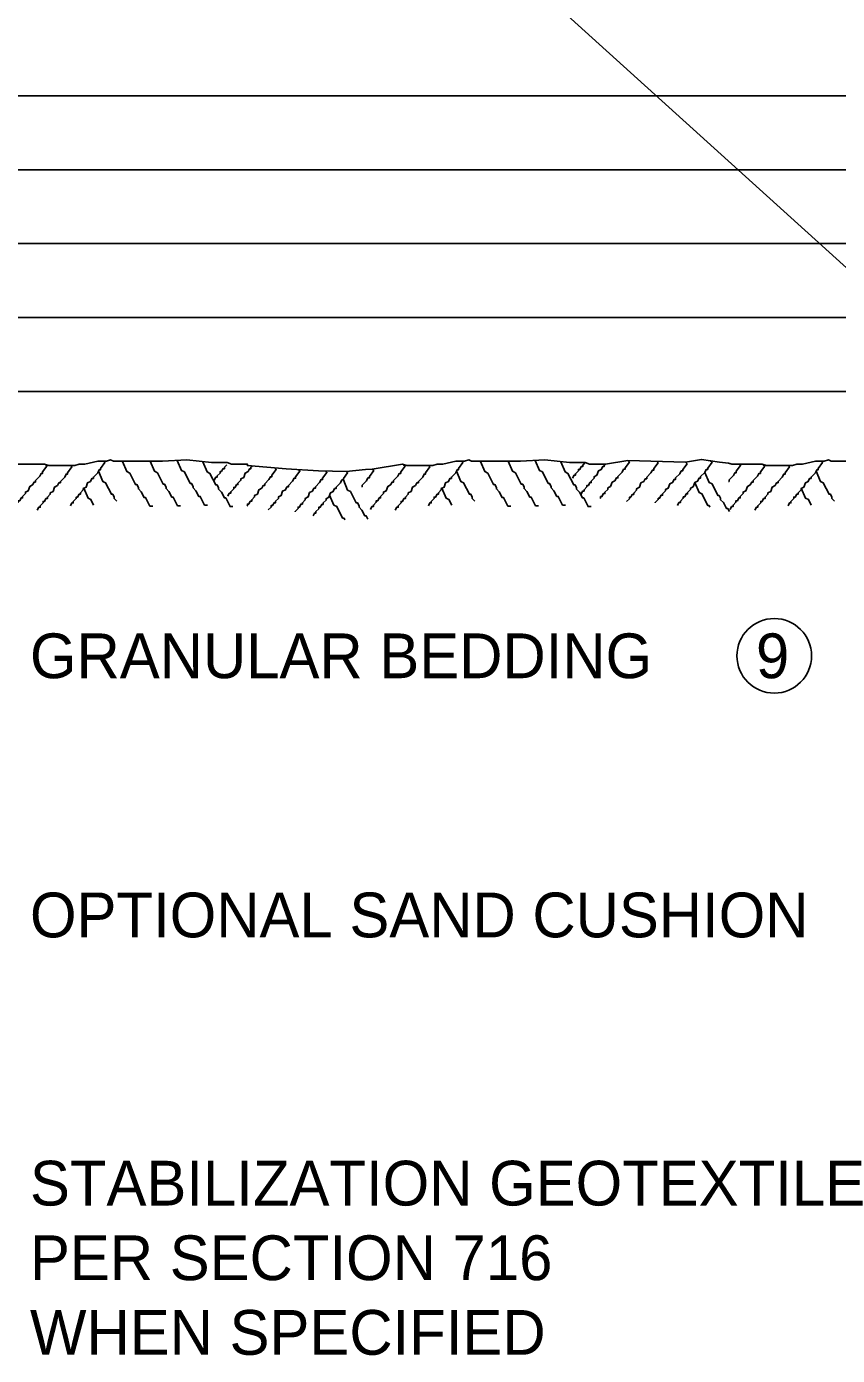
# Model space of a CAD drawing. Extents: x 49991.4 to 50021, y 49987.6 to 50011.4.
# Drawn here: x 50014.432 to 50015.519, y 50004.647 to 50006.427 of the extents above; entities that cross this region are included whole.
import ezdxf

# ---------------------------------------------------------------- set-up
doc = ezdxf.new("R2010")
doc.units = 0
doc.layers.add('Level 1', color=7, linetype='Continuous')
doc.layers.add('Level 2', color=7, linetype='Continuous')

msp = doc.modelspace()

# ---------------------------------------------------------------- linework, layer by layer
at = {"layer": 'Level 1'}
for p, q in [((50015.8403, 50005.8238), (50013.8839, 50007.5958)), ((50015.7342, 50006.3346), (50013.9592, 50006.3346)), ((50015.7342, 50006.2356), (50013.9592, 50006.2356)), ((50015.7342, 50006.1366), (50013.9592, 50006.1366)), ((50015.7342, 50006.0376), (50014.2021, 50006.0376)), ((50015.7342, 50005.9386), (50014.3195, 50005.9386))]:
    msp.add_line(p, q, dxfattribs=at)
for points in [[(50014.4579, 50005.8402), (50014.4598, 50005.8383), (50014.454, 50005.8306), (50014.454, 50005.8286), (50014.4522, 50005.8286), (50014.4502, 50005.8248), (50014.4444, 50005.819), (50014.4444, 50005.8171), (50014.4425, 50005.8171), (50014.4406, 50005.8132), (50014.4367, 50005.8113), (50014.4347, 50005.8055), (50014.4309, 50005.8036), (50014.4309, 50005.8016), (50014.427, 50005.7978), (50014.427, 50005.7959), (50014.4251, 50005.7959), (50014.4232, 50005.792), (50014.4213, 50005.792), (50014.4213, 50005.7901), (50014.4174, 50005.7862), (50014.4174, 50005.7843), (50014.4155, 50005.7843), (50014.4135, 50005.7805)], [(50014.4159, 50005.8412), (50014.4565, 50005.8412), (50014.4623, 50005.8392), (50014.497, 50005.8392), (50014.5028, 50005.8412), (50014.5105, 50005.8412), (50014.5278, 50005.845), (50014.5394, 50005.845), (50014.5451, 50005.8469), (50014.549, 50005.845), (50014.6088, 50005.845), (50014.6146, 50005.845), (50014.6474, 50005.8469), (50014.6801, 50005.8431), (50014.7013, 50005.8431), (50014.7071, 50005.8412), (50014.7206, 50005.8412), (50014.7283, 50005.8412), (50014.7283, 50005.8392), (50014.7801, 50005.8346), (50014.8235, 50005.832), (50014.8422, 50005.8317), (50014.8606, 50005.8314), (50014.8865, 50005.834)], [(50014.4912, 50005.8393), (50014.4931, 50005.8373), (50014.4873, 50005.8296), (50014.4873, 50005.8277), (50014.4854, 50005.8277), (50014.4835, 50005.8238), (50014.4777, 50005.818), (50014.4777, 50005.8161), (50014.4757, 50005.8161), (50014.4738, 50005.8123), (50014.47, 50005.8103), (50014.468, 50005.8046), (50014.4642, 50005.8026), (50014.4642, 50005.8007), (50014.4603, 50005.7969), (50014.4603, 50005.7949), (50014.4584, 50005.7949), (50014.4565, 50005.7911), (50014.4545, 50005.7911), (50014.4545, 50005.7891), (50014.4507, 50005.7853), (50014.4507, 50005.7834), (50014.4487, 50005.7834), (50014.4468, 50005.7795)], [(50014.5355, 50005.845), (50014.5374, 50005.8431), (50014.5317, 50005.8354), (50014.5317, 50005.8335), (50014.5297, 50005.8335), (50014.5278, 50005.8296), (50014.522, 50005.8238), (50014.522, 50005.8219), (50014.5201, 50005.8219), (50014.5181, 50005.818), (50014.5143, 50005.8161), (50014.5123, 50005.8103), (50014.5085, 50005.8084), (50014.5085, 50005.8065), (50014.5046, 50005.8026), (50014.5046, 50005.8007), (50014.5027, 50005.8007), (50014.5008, 50005.7969), (50014.4989, 50005.7969), (50014.4989, 50005.7949), (50014.495, 50005.7911), (50014.495, 50005.7891), (50014.4931, 50005.7891), (50014.4912, 50005.7853)], [(50014.5288, 50005.8315), (50014.5345, 50005.818), (50014.5384, 50005.8161), (50014.5461, 50005.8007), (50014.548, 50005.8007), (50014.55, 50005.7968), (50014.55, 50005.7949), (50014.5535, 50005.7914)], [(50014.5611, 50005.8446), (50014.5668, 50005.8311), (50014.5707, 50005.8291), (50014.5784, 50005.8137), (50014.5804, 50005.8137), (50014.5822, 50005.8098), (50014.5822, 50005.8079), (50014.5861, 50005.8041), (50014.59, 50005.7963), (50014.5919, 50005.7963), (50014.5977, 50005.7848), (50014.6015, 50005.7848)], [(50014.5981, 50005.845), (50014.6039, 50005.8315), (50014.6078, 50005.8296), (50014.6155, 50005.8142), (50014.6174, 50005.8142), (50014.6194, 50005.8103), (50014.6194, 50005.8084), (50014.6232, 50005.8046), (50014.6271, 50005.7968), (50014.629, 50005.7968), (50014.6348, 50005.7853), (50014.6387, 50005.7853)], [(50014.6343, 50005.846), (50014.6401, 50005.8325), (50014.6439, 50005.8306), (50014.6517, 50005.8152), (50014.6536, 50005.8152), (50014.6555, 50005.8113), (50014.6555, 50005.8094), (50014.6594, 50005.8055), (50014.6632, 50005.7978), (50014.6652, 50005.7978), (50014.6709, 50005.7862), (50014.6748, 50005.7862)], [(50014.6685, 50005.8441), (50014.6743, 50005.8306), (50014.6782, 50005.8286), (50014.6859, 50005.8132), (50014.6878, 50005.8132), (50014.6898, 50005.8094), (50014.6898, 50005.8074), (50014.6936, 50005.8036), (50014.6975, 50005.7959), (50014.6994, 50005.7959), (50014.7052, 50005.7843), (50014.709, 50005.7843)], [(50014.7009, 50005.8403), (50014.6975, 50005.8368), (50014.6975, 50005.8349), (50014.6955, 50005.8349), (50014.6936, 50005.8311), (50014.6917, 50005.8311), (50014.6917, 50005.8291), (50014.6878, 50005.8253), (50014.6878, 50005.8234), (50014.6859, 50005.8234), (50014.684, 50005.8195)], [(50014.7347, 50005.8384), (50014.7331, 50005.8368), (50014.7331, 50005.8349), (50014.7312, 50005.8349), (50014.7292, 50005.8311), (50014.7254, 50005.8291), (50014.7234, 50005.8233), (50014.7196, 50005.8214), (50014.7196, 50005.8194), (50014.7157, 50005.8156), (50014.7157, 50005.8137), (50014.7138, 50005.8137), (50014.7119, 50005.8098), (50014.71, 50005.8098), (50014.71, 50005.8079), (50014.7061, 50005.804), (50014.7061, 50005.8021), (50014.7041, 50005.8021), (50014.7022, 50005.7982)], [(50014.765, 50005.8357), (50014.7669, 50005.8338), (50014.7611, 50005.8261), (50014.7611, 50005.8242), (50014.7592, 50005.8242), (50014.7572, 50005.8203), (50014.7515, 50005.8145), (50014.7515, 50005.8126), (50014.7495, 50005.8126), (50014.7476, 50005.8087), (50014.7438, 50005.8068), (50014.7418, 50005.801), (50014.7379, 50005.7991), (50014.7379, 50005.7972), (50014.7341, 50005.7933), (50014.7341, 50005.7914), (50014.7322, 50005.7914), (50014.7302, 50005.7875), (50014.7283, 50005.7875), (50014.7283, 50005.7856), (50014.7277, 50005.785)], [(50014.7968, 50005.8338), (50014.7987, 50005.8318), (50014.7929, 50005.8241), (50014.7929, 50005.8222), (50014.791, 50005.8222), (50014.789, 50005.8184), (50014.7833, 50005.8126), (50014.7833, 50005.8106), (50014.7814, 50005.8106), (50014.7794, 50005.8068), (50014.7756, 50005.8049), (50014.7736, 50005.799), (50014.7698, 50005.7971), (50014.7698, 50005.7952), (50014.766, 50005.7913), (50014.766, 50005.7894), (50014.764, 50005.7894), (50014.7621, 50005.7856), (50014.7601, 50005.7856), (50014.7601, 50005.7836), (50014.7562, 50005.7798)], [(50014.8329, 50005.8318), (50014.8348, 50005.8299), (50014.829, 50005.8222), (50014.829, 50005.8203), (50014.8271, 50005.8203), (50014.8251, 50005.8164), (50014.8194, 50005.8106), (50014.8194, 50005.8087), (50014.8174, 50005.8087), (50014.8155, 50005.8048), (50014.8117, 50005.8029), (50014.8097, 50005.7971), (50014.8058, 50005.7952), (50014.8058, 50005.7932), (50014.802, 50005.7894), (50014.802, 50005.7875), (50014.8001, 50005.7875), (50014.7982, 50005.7836), (50014.7962, 50005.7836), (50014.7962, 50005.7817), (50014.7924, 50005.7778), (50014.7924, 50005.7772)], [(50014.8606, 50005.8314), (50014.8626, 50005.8295), (50014.8569, 50005.8218), (50014.8569, 50005.8199), (50014.8549, 50005.8199), (50014.853, 50005.816), (50014.8472, 50005.8102), (50014.8472, 50005.8083), (50014.8452, 50005.8083), (50014.8433, 50005.8044), (50014.8395, 50005.8025), (50014.8376, 50005.7967), (50014.8337, 50005.7948), (50014.8337, 50005.7928), (50014.8298, 50005.789), (50014.8298, 50005.7871), (50014.8279, 50005.7871), (50014.826, 50005.7832), (50014.824, 50005.7832), (50014.824, 50005.7813), (50014.8202, 50005.7774), (50014.8202, 50005.7755), (50014.8182, 50005.7755), (50014.8164, 50005.7716)], [(50014.8957, 50005.8343), (50014.8976, 50005.8324), (50014.8918, 50005.8247), (50014.8918, 50005.8227), (50014.8899, 50005.8227), (50014.888, 50005.8189), (50014.8822, 50005.8131), (50014.8822, 50005.8111), (50014.8812, 50005.8111)], [(50014.8865, 50005.834), (50014.8957, 50005.8343), (50014.9362, 50005.8412), (50014.942, 50005.8392), (50014.9767, 50005.8392), (50014.9825, 50005.8412), (50014.9902, 50005.8412), (50015.0075, 50005.845), (50015.0191, 50005.845), (50015.0249, 50005.8469), (50015.0288, 50005.845), (50015.0885, 50005.845), (50015.0943, 50005.845), (50015.1271, 50005.8469), (50015.1599, 50005.8431), (50015.1811, 50005.8431), (50015.1868, 50005.8412), (50015.2003, 50005.8412), (50015.208, 50005.8412), (50015.2383, 50005.8459), (50015.3154, 50005.8436), (50015.3367, 50005.8473), (50015.3611, 50005.8436), (50015.3728, 50005.8424), (50015.3752, 50005.8418)], [(50014.9376, 50005.8402), (50014.9396, 50005.8383), (50014.9338, 50005.8306), (50014.9338, 50005.8286), (50014.9319, 50005.8286), (50014.9299, 50005.8248), (50014.9242, 50005.819), (50014.9242, 50005.8171), (50014.9222, 50005.8171), (50014.9203, 50005.8132), (50014.9164, 50005.8113), (50014.9145, 50005.8055), (50014.9106, 50005.8036), (50014.9106, 50005.8016), (50014.9068, 50005.7978), (50014.9068, 50005.7959), (50014.9049, 50005.7959), (50014.903, 50005.792), (50014.901, 50005.792), (50014.901, 50005.7901), (50014.8971, 50005.7862), (50014.8971, 50005.7843), (50014.8952, 50005.7843), (50014.8933, 50005.7805)], [(50014.9709, 50005.8393), (50014.9728, 50005.8373), (50014.967, 50005.8296), (50014.967, 50005.8277), (50014.9651, 50005.8277), (50014.9632, 50005.8238), (50014.9574, 50005.818), (50014.9574, 50005.8161), (50014.9554, 50005.8161), (50014.9535, 50005.8123), (50014.9497, 50005.8103), (50014.9477, 50005.8046), (50014.9439, 50005.8026), (50014.9439, 50005.8007), (50014.94, 50005.7969), (50014.94, 50005.7949), (50014.9381, 50005.7949), (50014.9362, 50005.7911), (50014.9343, 50005.7911), (50014.9343, 50005.7891), (50014.9304, 50005.7853), (50014.9304, 50005.7834), (50014.9284, 50005.7834), (50014.9265, 50005.7795)], [(50015.0152, 50005.845), (50015.0171, 50005.8431), (50015.0114, 50005.8354), (50015.0114, 50005.8335), (50015.0094, 50005.8335), (50015.0075, 50005.8296), (50015.0017, 50005.8238), (50015.0017, 50005.8219), (50014.9998, 50005.8219), (50014.9979, 50005.818), (50014.994, 50005.8161), (50014.9921, 50005.8103), (50014.9882, 50005.8084), (50014.9882, 50005.8065), (50014.9844, 50005.8026), (50014.9844, 50005.8007), (50014.9825, 50005.8007), (50014.9805, 50005.7969), (50014.9786, 50005.7969), (50014.9786, 50005.7949), (50014.9748, 50005.7911), (50014.9748, 50005.7891), (50014.9728, 50005.7891), (50014.9709, 50005.7853)], [(50015.0085, 50005.8315), (50015.0143, 50005.818), (50015.0181, 50005.8161), (50015.0258, 50005.8007), (50015.0278, 50005.8007), (50015.0297, 50005.7968), (50015.0297, 50005.7949), (50015.0333, 50005.7914)], [(50015.0408, 50005.8446), (50015.0465, 50005.8311), (50015.0504, 50005.8291), (50015.0581, 50005.8137), (50015.0601, 50005.8137), (50015.062, 50005.8098), (50015.062, 50005.8079), (50015.0658, 50005.8041), (50015.0697, 50005.7963), (50015.0716, 50005.7963), (50015.0774, 50005.7848), (50015.0813, 50005.7848)], [(50015.0779, 50005.845), (50015.0837, 50005.8315), (50015.0875, 50005.8296), (50015.0952, 50005.8142), (50015.0972, 50005.8142), (50015.0991, 50005.8103), (50015.0991, 50005.8084), (50015.103, 50005.8046), (50015.1068, 50005.7968), (50015.1087, 50005.7968), (50015.1145, 50005.7853), (50015.1184, 50005.7853)], [(50015.114, 50005.846), (50015.1198, 50005.8325), (50015.1237, 50005.8306), (50015.1314, 50005.8152), (50015.1333, 50005.8152), (50015.1352, 50005.8113), (50015.1352, 50005.8094), (50015.1391, 50005.8055), (50015.143, 50005.7978), (50015.1449, 50005.7978), (50015.1507, 50005.7862), (50015.1545, 50005.7862)], [(50015.1483, 50005.8441), (50015.154, 50005.8306), (50015.1579, 50005.8286), (50015.1656, 50005.8132), (50015.1675, 50005.8132), (50015.1695, 50005.8094), (50015.1695, 50005.8074), (50015.1733, 50005.8036), (50015.1772, 50005.7959), (50015.1791, 50005.7959), (50015.1849, 50005.7843), (50015.1888, 50005.7843)], [(50015.1811, 50005.8431), (50015.1776, 50005.8396), (50015.1776, 50005.8377), (50015.1756, 50005.8377), (50015.1738, 50005.8339), (50015.1718, 50005.8339), (50015.1718, 50005.8319), (50015.1679, 50005.8281), (50015.1679, 50005.8262), (50015.166, 50005.8262), (50015.1641, 50005.8223)], [(50015.208, 50005.8412), (50015.2064, 50005.8396), (50015.2064, 50005.8377), (50015.2045, 50005.8377), (50015.2026, 50005.8338), (50015.1988, 50005.8319), (50015.1968, 50005.8261), (50015.1929, 50005.8242), (50015.1929, 50005.8222), (50015.1891, 50005.8184), (50015.1891, 50005.8164), (50015.1872, 50005.8164), (50015.1852, 50005.8126), (50015.1833, 50005.8126), (50015.1833, 50005.8107), (50015.1795, 50005.8068), (50015.1795, 50005.8049), (50015.1775, 50005.8049), (50015.1756, 50005.801)], [(50015.2383, 50005.8459), (50015.2402, 50005.8439), (50015.2344, 50005.8362), (50015.2344, 50005.8343), (50015.2325, 50005.8343), (50015.2305, 50005.8304), (50015.2248, 50005.8246), (50015.2248, 50005.8227), (50015.2228, 50005.8227), (50015.2209, 50005.8189), (50015.2171, 50005.8169), (50015.2151, 50005.8112), (50015.2113, 50005.8092), (50015.2113, 50005.8073), (50015.2074, 50005.8035), (50015.2074, 50005.8016), (50015.2055, 50005.8016), (50015.2035, 50005.7977), (50015.2017, 50005.7977), (50015.2017, 50005.7957), (50015.201, 50005.7951)], [(50015.2769, 50005.8448), (50015.2788, 50005.8428), (50015.273, 50005.8351), (50015.273, 50005.8332), (50015.2711, 50005.8332), (50015.2691, 50005.8293), (50015.2634, 50005.8236), (50015.2634, 50005.8216), (50015.2614, 50005.8216), (50015.2595, 50005.8178), (50015.2556, 50005.8159), (50015.2537, 50005.81), (50015.2499, 50005.8081), (50015.2499, 50005.8062), (50015.246, 50005.8023), (50015.246, 50005.8004), (50015.2441, 50005.8004), (50015.2421, 50005.7966), (50015.2402, 50005.7966), (50015.2402, 50005.7946), (50015.2363, 50005.7908)], [(50015.3154, 50005.8436), (50015.3174, 50005.8417), (50015.3116, 50005.834), (50015.3116, 50005.8321), (50015.3097, 50005.8321), (50015.3077, 50005.8282), (50015.302, 50005.8225), (50015.302, 50005.8205), (50015.3, 50005.8205), (50015.2981, 50005.8166), (50015.2943, 50005.8147), (50015.2923, 50005.8089), (50015.2884, 50005.807), (50015.2884, 50005.8051), (50015.2846, 50005.8012), (50015.2846, 50005.7993), (50015.2827, 50005.7993), (50015.2807, 50005.7954), (50015.2788, 50005.7954), (50015.2788, 50005.7935), (50015.2749, 50005.7896), (50015.2749, 50005.789)], [(50015.3489, 50005.8455), (50015.3509, 50005.8435), (50015.3452, 50005.8358), (50015.3452, 50005.8339), (50015.3432, 50005.8339), (50015.3413, 50005.83), (50015.3355, 50005.8243), (50015.3355, 50005.8223), (50015.3335, 50005.8223), (50015.3316, 50005.8184), (50015.3277, 50005.8165), (50015.3258, 50005.8108), (50015.322, 50005.8088), (50015.322, 50005.8069), (50015.3181, 50005.803), (50015.3181, 50005.8011), (50015.3162, 50005.8011), (50015.3143, 50005.7972), (50015.3123, 50005.7972), (50015.3123, 50005.7953), (50015.3085, 50005.7914), (50015.3085, 50005.7895), (50015.3065, 50005.7895), (50015.3047, 50005.7857)], [(50015.3728, 50005.8424), (50015.3776, 50005.8412), (50015.4181, 50005.8412), (50015.4239, 50005.8392), (50015.4587, 50005.8392), (50015.4644, 50005.8412), (50015.4721, 50005.8412), (50015.4895, 50005.845), (50015.501, 50005.845), (50015.5068, 50005.8469), (50015.5107, 50005.845), (50015.5704, 50005.845)], [(50015.3873, 50005.8412), (50015.3892, 50005.8393), (50015.3834, 50005.8315), (50015.3834, 50005.8296), (50015.3815, 50005.8296), (50015.3796, 50005.8258), (50015.3738, 50005.82), (50015.3738, 50005.818), (50015.3728, 50005.818)], [(50015.4196, 50005.8402), (50015.4215, 50005.8383), (50015.4157, 50005.8306), (50015.4157, 50005.8286), (50015.4138, 50005.8286), (50015.4119, 50005.8248), (50015.4061, 50005.819), (50015.4061, 50005.8171), (50015.4042, 50005.8171), (50015.4022, 50005.8132), (50015.3984, 50005.8113), (50015.3964, 50005.8055), (50015.3926, 50005.8036), (50015.3926, 50005.8016), (50015.3887, 50005.7978), (50015.3887, 50005.7959), (50015.3868, 50005.7959), (50015.3849, 50005.792), (50015.3829, 50005.792), (50015.3829, 50005.7901), (50015.3791, 50005.7862), (50015.3791, 50005.7843), (50015.3771, 50005.7843), (50015.3752, 50005.7805)], [(50015.4528, 50005.8393), (50015.4547, 50005.8373), (50015.449, 50005.8296), (50015.449, 50005.8277), (50015.447, 50005.8277), (50015.4451, 50005.8238), (50015.4394, 50005.818), (50015.4394, 50005.8161), (50015.4374, 50005.8161), (50015.4355, 50005.8123), (50015.4316, 50005.8103), (50015.4297, 50005.8046), (50015.4258, 50005.8026), (50015.4258, 50005.8007), (50015.422, 50005.7969), (50015.422, 50005.7949), (50015.4201, 50005.7949), (50015.4181, 50005.7911), (50015.4162, 50005.7911), (50015.4162, 50005.7891), (50015.4123, 50005.7853), (50015.4123, 50005.7834), (50015.4104, 50005.7834), (50015.4085, 50005.7795)], [(50015.4972, 50005.845), (50015.4991, 50005.8431), (50015.4933, 50005.8354), (50015.4933, 50005.8335), (50015.4914, 50005.8335), (50015.4895, 50005.8296), (50015.4837, 50005.8238), (50015.4837, 50005.8219), (50015.4817, 50005.8219), (50015.4798, 50005.818), (50015.476, 50005.8161), (50015.474, 50005.8103), (50015.4702, 50005.8084), (50015.4702, 50005.8065), (50015.4663, 50005.8026), (50015.4663, 50005.8007), (50015.4644, 50005.8007), (50015.4624, 50005.7969), (50015.4605, 50005.7969), (50015.4605, 50005.7949), (50015.4567, 50005.7911), (50015.4567, 50005.7891), (50015.4547, 50005.7891), (50015.4528, 50005.7853)], [(50015.4904, 50005.8315), (50015.4962, 50005.818), (50015.5, 50005.8161), (50015.5078, 50005.8007), (50015.5097, 50005.8007), (50015.5116, 50005.7968), (50015.5116, 50005.7949), (50015.5152, 50005.7914)], [(50014.8569, 50005.8199), (50014.8626, 50005.8064), (50014.8665, 50005.8044), (50014.8742, 50005.789), (50014.8761, 50005.789), (50014.8781, 50005.7851), (50014.8781, 50005.7832), (50014.8819, 50005.7794), (50014.8858, 50005.7717), (50014.8877, 50005.7717), (50014.8899, 50005.7673)], [(50015.3277, 50005.8165), (50015.3335, 50005.803), (50015.3374, 50005.8011), (50015.3451, 50005.7857), (50015.3471, 50005.7857), (50015.3481, 50005.7835)], [(50015.3413, 50005.83), (50015.347, 50005.8165), (50015.3509, 50005.8146), (50015.3586, 50005.7991), (50015.3605, 50005.7991), (50015.3625, 50005.7953), (50015.3625, 50005.7934), (50015.3663, 50005.7895), (50015.3702, 50005.7818), (50015.3721, 50005.7818), (50015.3743, 50005.7774)], [(50014.509, 50005.8089), (50014.5148, 50005.7954), (50014.5186, 50005.7935), (50014.5223, 50005.786)], [(50014.8385, 50005.7996), (50014.8443, 50005.7861), (50014.8482, 50005.7842), (50014.8558, 50005.7688), (50014.8578, 50005.7688), (50014.8589, 50005.7666)], [(50014.9887, 50005.8089), (50014.9945, 50005.7954), (50014.9984, 50005.7935), (50015.0021, 50005.786)], [(50015.4706, 50005.8089), (50015.4764, 50005.7954), (50015.4803, 50005.7935), (50015.484, 50005.786)]]:
    msp.add_lwpolyline(points, dxfattribs=at)
at = {"layer": 'Level 2'}
msp.add_circle((50015.4343, 50005.5842), 0.05, dxfattribs=at)

# ---------------------------------------------------------------- texts
for s, p in [('GRANULAR BEDDING', (50014.437, 50005.5542)), ('9', (50015.4098, 50005.5542)), ('OPTIONAL SAND CUSHION', (50014.437, 50005.2069)), ('STABILIZATION GEOTEXTILE', (50014.437, 50004.8475)), ('PER SECTION 716', (50014.437, 50004.7475)), ('WHEN SPECIFIED', (50014.437, 50004.6475))]:
    msp.add_text(s, height=0.06, dxfattribs=at).set_placement(p)

doc.saveas('drawing.dxf')
